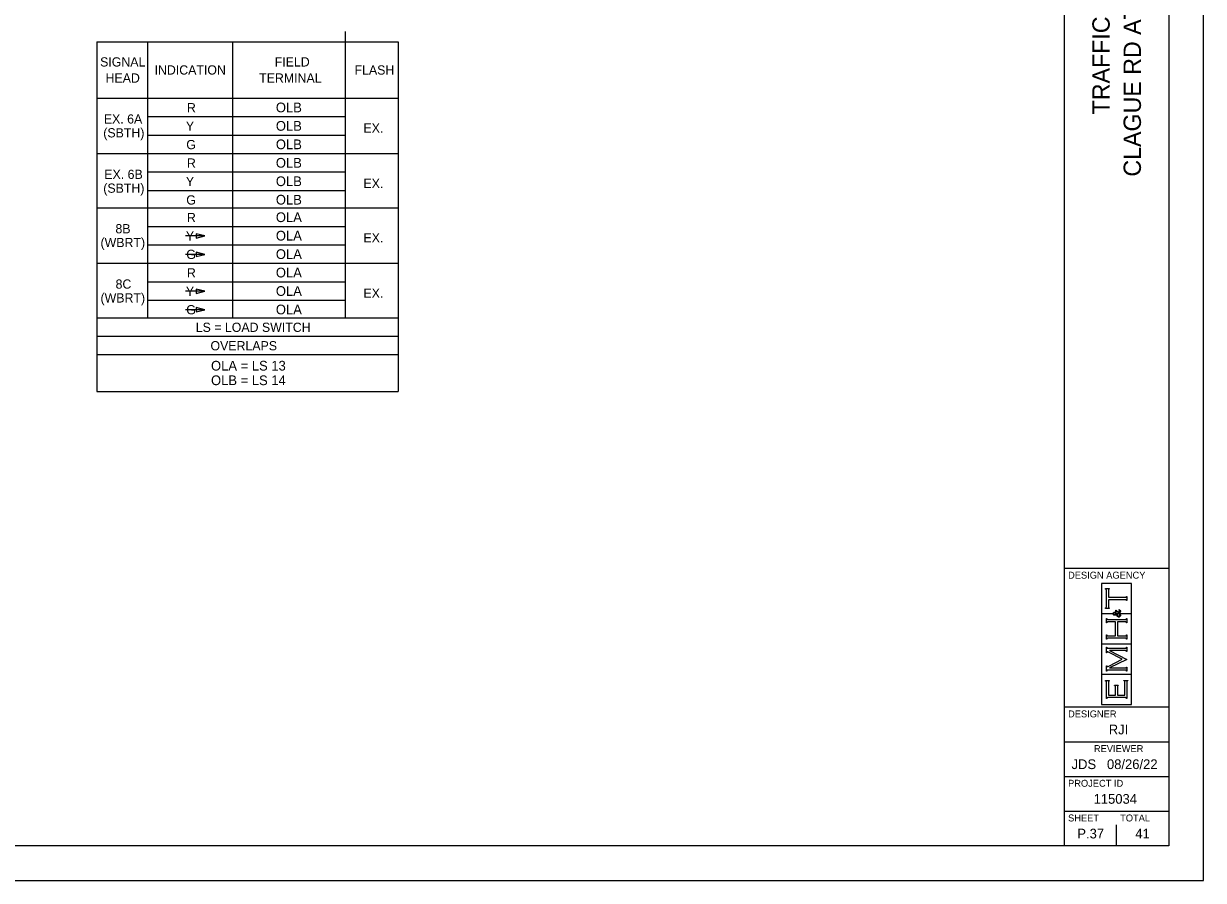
# Model space of a CAD drawing. Extents: x 680 to 2132, y 0 to 656.
# Drawn here: x 1020 to 1360, y 0 to 247 of the extents above; entities that cross this region are included whole.
import ezdxf

# ---------------------------------------------------------------- set-up
doc = ezdxf.new("R2010")
doc.units = 0
for name, color, linetype in [('SH_Border', 7, 'Continuous'), ('SH_Cut_Line', 7, 'Continuous'), ('SH_Data', 7, 'Continuous'), ('SH_Text', 7, 'Continuous'), ('ST_Text', 7, 'Continuous')]:
    doc.layers.add(name, color=color, linetype=linetype)

msp = doc.modelspace()

# ---------------------------------------------------------------- linework, layer by layer
at = {"layer": 'SH_Border'}
for p, q in [((1320, 10), (1320, 430)), ((1320, 90), (1350, 90)), ((1320, 50), (1350, 50)), ((1320, 40), (1350, 40)), ((1320, 30), (1350, 30)), ((1320, 20), (1350, 20))]:
    msp.add_line(p, q, dxfattribs=at)
msp.add_lwpolyline([(710, 430), (1350, 430), (1350, 10), (710, 10)], close=True, dxfattribs=at)
at = {"layer": 'SH_Cut_Line'}
msp.add_lwpolyline([(680, 0), (1360, 0), (1360, 440), (680, 440)], close=True, dxfattribs=at)
at = {"layer": 'SH_Data'}
for p, q in [((1072.23, 185.81), (1066.67, 185.81)), ((1072.23, 180.49), (1066.67, 180.49)), ((1072.23, 169.85), (1066.67, 169.85)), ((1072.23, 164.53), (1066.67, 164.53)), ((1339.32, 85.59), (1330.68, 85.59)), ((1330.68, 85.59), (1330.68, 76.96)), ((1339.32, 76.96), (1339.32, 85.59)), ((1331.77, 83.99), (1331.77, 84.13)), ((1331.77, 84.13), (1332.89, 84.13)), ((1331.88, 83.96), (1331.77, 83.99)), ((1331.95, 83.92), (1331.88, 83.96)), ((1331.99, 83.87), (1331.95, 83.92)), ((1332.02, 83.82), (1331.99, 83.87)), ((1332.04, 83.74), (1332.02, 83.82)), ((1332.04, 83.62), (1332.04, 83.74)), ((1332.04, 78.94), (1332.04, 83.62)), ((1332.63, 83.82), (1332.61, 83.74)), ((1332.61, 83.74), (1332.61, 83.62)), ((1332.61, 83.62), (1332.61, 81.62)), ((1332.61, 81.62), (1337.45, 81.62)), ((1332.67, 83.87), (1332.63, 83.82)), ((1332.7, 83.92), (1332.67, 83.87)), ((1332.78, 83.96), (1332.7, 83.92)), ((1332.89, 83.99), (1332.78, 83.96)), ((1332.89, 84.13), (1332.89, 83.99)), ((1337.45, 81.62), (1337.56, 81.62)), ((1337.56, 81.62), (1337.65, 81.63)), ((1337.65, 81.63), (1337.7, 81.67)), ((1337.7, 81.67), (1337.75, 81.71)), ((1337.75, 81.71), (1337.79, 81.78)), ((1337.79, 81.78), (1337.82, 81.89)), ((1337.82, 81.89), (1337.96, 81.89)), ((1337.96, 81.89), (1337.96, 80.66)), ((1331.77, 78.57), (1331.88, 78.59)), ((1331.77, 78.43), (1331.77, 78.57)), ((1332.89, 78.43), (1331.77, 78.43)), ((1331.88, 78.59), (1331.95, 78.63)), ((1331.95, 78.63), (1331.99, 78.68)), ((1331.99, 78.68), (1332.02, 78.73)), ((1332.02, 78.73), (1332.04, 78.82)), ((1332.04, 78.82), (1332.04, 78.94)), ((1337.45, 80.94), (1332.61, 80.94)), ((1332.61, 80.94), (1332.61, 78.94)), ((1332.61, 78.94), (1332.61, 78.82)), ((1332.61, 78.82), (1332.63, 78.73)), ((1332.63, 78.73), (1332.67, 78.68)), ((1332.67, 78.68), (1332.7, 78.63)), ((1332.7, 78.63), (1332.78, 78.59)), ((1332.78, 78.59), (1332.89, 78.57)), ((1332.89, 78.57), (1332.89, 78.43)), ((1337.57, 80.94), (1337.45, 80.94)), ((1337.65, 80.92), (1337.57, 80.94)), ((1337.7, 80.88), (1337.65, 80.92)), ((1337.75, 80.84), (1337.7, 80.88)), ((1337.79, 80.77), (1337.75, 80.84)), ((1337.82, 80.66), (1337.79, 80.77)), ((1337.96, 80.66), (1337.82, 80.66)), ((1330.68, 76.96), (1333.86, 76.96)), ((1333.85, 76.84), (1330.68, 76.84)), ((1330.68, 76.84), (1330.68, 68.21)), ((1332.04, 74.28), (1332.04, 75.51)), ((1332.04, 75.51), (1332.18, 75.51)), ((1332.18, 75.51), (1332.21, 75.4)), ((1332.21, 75.4), (1332.25, 75.33)), ((1332.25, 75.33), (1332.3, 75.29)), ((1332.3, 75.29), (1332.35, 75.25)), ((1332.35, 75.25), (1332.43, 75.24)), ((1332.43, 75.24), (1332.55, 75.24)), ((1332.55, 75.24), (1337.45, 75.24)), ((1333.86, 76.96), (1333.85, 76.84)), ((1334.02, 77.04), (1334.06, 77.14)), ((1334.02, 76.93), (1334.02, 77.04)), ((1334.02, 76.81), (1334.02, 76.93)), ((1334.05, 76.7), (1334.02, 76.81)), ((1334.12, 76.61), (1334.05, 76.7)), ((1334.06, 77.14), (1334.12, 77.21)), ((1334.12, 77.21), (1334.19, 77.28)), ((1334.21, 76.49), (1334.12, 76.61)), ((1334.15, 77.04), (1334.13, 76.99)), ((1334.13, 76.99), (1334.13, 76.93)), ((1334.13, 76.93), (1334.13, 76.84)), ((1334.13, 76.84), (1334.15, 76.78)), ((1334.19, 77.09), (1334.15, 77.04)), ((1334.15, 76.78), (1334.21, 76.74)), ((1334.19, 77.28), (1334.27, 77.32)), ((1334.24, 77.13), (1334.19, 77.09)), ((1334.21, 76.74), (1334.27, 76.69)), ((1334.33, 76.43), (1334.21, 76.49)), ((1334.3, 77.15), (1334.24, 77.13)), ((1334.27, 77.32), (1334.37, 77.32)), ((1334.27, 76.69), (1334.33, 76.67)), ((1334.37, 77.15), (1334.3, 77.15)), ((1334.33, 76.67), (1334.38, 76.67)), ((1334.5, 76.43), (1334.33, 76.43)), ((1334.37, 77.32), (1334.47, 77.32)), ((1334.45, 77.15), (1334.37, 77.15)), ((1334.38, 76.67), (1334.43, 76.67)), ((1334.43, 76.67), (1334.49, 76.68)), ((1334.54, 77.12), (1334.45, 77.15)), ((1334.47, 77.32), (1334.56, 77.28)), ((1334.49, 76.68), (1334.54, 76.7)), ((1334.56, 76.43), (1334.5, 76.43)), ((1334.61, 77.06), (1334.54, 77.12)), ((1334.54, 76.7), (1334.6, 76.71)), ((1334.56, 77.28), (1334.64, 77.21)), ((1334.62, 76.43), (1334.56, 76.43)), ((1334.6, 76.71), (1334.69, 76.74)), ((1334.68, 77), (1334.61, 77.06)), ((1334.68, 76.45), (1334.62, 76.43)), ((1334.64, 77.21), (1334.72, 77.14)), ((1334.75, 76.91), (1334.68, 77)), ((1334.75, 76.47), (1334.68, 76.45)), ((1334.69, 76.74), (1334.8, 76.79)), ((1334.72, 77.14), (1334.8, 77.02)), ((1334.8, 76.79), (1334.75, 76.91)), ((1334.83, 76.5), (1334.75, 76.47)), ((1334.76, 77.35), (1334.76, 77.96)), ((1334.76, 77.96), (1334.82, 77.96)), ((1334.82, 77.35), (1334.76, 77.35)), ((1334.8, 77.02), (1334.89, 76.84)), ((1334.82, 77.96), (1334.82, 77.87)), ((1334.82, 77.87), (1334.84, 77.81)), ((1334.84, 77.42), (1334.82, 77.39)), ((1334.82, 77.39), (1334.82, 77.35)), ((1334.93, 76.54), (1334.83, 76.5)), ((1334.84, 77.81), (1334.87, 77.77)), ((1334.86, 77.44), (1334.84, 77.42)), ((1334.9, 77.47), (1334.86, 77.44)), ((1334.87, 77.77), (1334.9, 77.73)), ((1334.89, 76.84), (1335.11, 76.96)), ((1334.9, 77.73), (1334.99, 77.67)), ((1334.94, 77.48), (1334.9, 77.47)), ((1335.05, 76.31), (1334.93, 76.54)), ((1334.98, 77.48), (1334.94, 77.48)), ((1335.12, 77.48), (1334.98, 77.48)), ((1334.99, 77.67), (1335.15, 77.58)), ((1335.14, 76.65), (1335.03, 76.59)), ((1335.03, 76.59), (1335.09, 76.47)), ((1335.17, 76.15), (1335.05, 76.31)), ((1335.09, 76.47), (1335.17, 76.39)), ((1335.11, 76.96), (1335.31, 77.09)), ((1335.29, 77.4), (1335.12, 77.48)), ((1335.24, 76.7), (1335.14, 76.65)), ((1335.15, 77.58), (1335.3, 77.5)), ((1335.17, 76.39), (1335.25, 76.33)), ((1335.29, 76.07), (1335.17, 76.15)), ((1335.32, 76.75), (1335.24, 76.7)), ((1335.25, 76.33), (1335.33, 76.27)), ((1335.49, 77.23), (1335.29, 77.4)), ((1335.41, 75.99), (1335.29, 76.07)), ((1335.3, 77.5), (1335.44, 77.4)), ((1335.31, 77.09), (1335.49, 77.23)), ((1335.4, 76.8), (1335.32, 76.75)), ((1335.33, 76.27), (1335.41, 76.24)), ((1335.53, 76.89), (1335.4, 76.8)), ((1335.41, 76.24), (1335.51, 76.24)), ((1335.52, 75.94), (1335.41, 75.99)), ((1335.44, 77.4), (1335.57, 77.29)), ((1335.51, 76.24), (1335.61, 76.24)), ((1335.64, 75.94), (1335.52, 75.94)), ((1335.7, 77.02), (1335.53, 76.89)), ((1335.57, 77.29), (1335.67, 77.38)), ((1335.61, 76.24), (1335.7, 76.28)), ((1335.63, 77.99), (1335.67, 78.05)), ((1335.7, 77.97), (1335.63, 77.99)), ((1335.76, 75.94), (1335.64, 75.94)), ((1335.67, 78.05), (1335.8, 78.01)), ((1335.67, 77.38), (1335.74, 77.46)), ((1335.75, 77.94), (1335.7, 77.97)), ((1335.78, 76.92), (1335.7, 77.02)), ((1335.7, 76.28), (1335.78, 76.34)), ((1335.74, 77.46), (1335.78, 77.52)), ((1335.79, 77.89), (1335.75, 77.94)), ((1335.86, 75.99), (1335.76, 75.94)), ((1335.78, 77.52), (1335.82, 77.59)), ((1335.89, 77.19), (1335.78, 77.09)), ((1335.78, 77.09), (1335.89, 76.97)), ((1335.83, 76.84), (1335.78, 76.92)), ((1335.78, 76.34), (1335.86, 76.41)), ((1335.82, 77.85), (1335.79, 77.89)), ((1335.8, 78.01), (1335.9, 77.95)), ((1335.84, 77.79), (1335.82, 77.85)), ((1335.82, 77.59), (1335.84, 77.66)), ((1335.86, 76.79), (1335.83, 76.84)), ((1335.84, 77.73), (1335.84, 77.79)), ((1335.84, 77.66), (1335.84, 77.73)), ((1335.88, 76.73), (1335.86, 76.79)), ((1335.86, 76.41), (1335.9, 76.5)), ((1335.94, 76.08), (1335.86, 75.99)), ((1335.9, 76.67), (1335.88, 76.73)), ((1335.96, 77.28), (1335.89, 77.19)), ((1335.89, 76.97), (1335.97, 76.87)), ((1335.9, 77.95), (1335.97, 77.87)), ((1335.9, 76.61), (1335.9, 76.67)), ((1335.9, 76.5), (1335.9, 76.61)), ((1336.03, 76.18), (1335.94, 76.08)), ((1336, 77.36), (1335.96, 77.28)), ((1335.97, 77.87), (1336.04, 77.8)), ((1335.97, 76.87), (1336.01, 76.77)), ((1336.05, 77.44), (1336, 77.36)), ((1336.01, 76.77), (1336.05, 76.67)), ((1336.07, 76.3), (1336.03, 76.18)), ((1336.04, 77.8), (1336.07, 77.7)), ((1336.07, 77.52), (1336.05, 77.44)), ((1336.05, 76.67), (1336.07, 76.57)), ((1336.14, 76.84), (1336.06, 76.96)), ((1336.06, 76.96), (1339.32, 76.96)), ((1336.07, 77.7), (1336.07, 77.6)), ((1336.07, 77.6), (1336.07, 77.52)), ((1336.07, 76.57), (1336.07, 76.46)), ((1336.07, 76.46), (1336.07, 76.3)), ((1339.32, 76.84), (1336.14, 76.84)), ((1337.45, 75.24), (1337.56, 75.24)), ((1337.56, 75.24), (1337.65, 75.25)), ((1337.65, 75.25), (1337.7, 75.29)), ((1337.7, 75.29), (1337.75, 75.33)), ((1337.75, 75.33), (1337.79, 75.4)), ((1337.79, 75.4), (1337.82, 75.51)), ((1337.82, 75.51), (1337.96, 75.51)), ((1337.96, 75.51), (1337.96, 74.28)), ((1339.32, 68.21), (1339.32, 76.84)), ((1332.18, 74.28), (1332.04, 74.28)), ((1332.21, 74.39), (1332.18, 74.28)), ((1332.25, 74.46), (1332.21, 74.39)), ((1332.3, 74.5), (1332.25, 74.46)), ((1332.35, 74.54), (1332.3, 74.5)), ((1332.43, 74.56), (1332.35, 74.54)), ((1332.55, 74.56), (1332.43, 74.56)), ((1334.63, 74.56), (1332.55, 74.56)), ((1334.63, 70.49), (1334.63, 74.56)), ((1337.45, 74.56), (1335.2, 74.56)), ((1335.2, 74.56), (1335.2, 70.49)), ((1337.57, 74.56), (1337.45, 74.56)), ((1337.65, 74.54), (1337.57, 74.56)), ((1337.7, 74.5), (1337.65, 74.54)), ((1337.75, 74.46), (1337.7, 74.5)), ((1337.79, 74.39), (1337.75, 74.46)), ((1337.82, 74.28), (1337.79, 74.39)), ((1337.96, 74.28), (1337.82, 74.28)), ((1330.68, 68.21), (1339.32, 68.21)), ((1339.32, 68.09), (1330.68, 68.09)), ((1330.68, 68.09), (1330.68, 59.45)), ((1332.04, 69.54), (1332.04, 70.77)), ((1332.04, 70.77), (1332.18, 70.77)), ((1332.18, 69.54), (1332.04, 69.54)), ((1332.18, 70.77), (1332.21, 70.66)), ((1332.21, 69.65), (1332.18, 69.54)), ((1332.21, 70.66), (1332.25, 70.59)), ((1332.25, 69.72), (1332.21, 69.65)), ((1332.25, 70.59), (1332.3, 70.55)), ((1332.3, 69.76), (1332.25, 69.72)), ((1332.3, 70.55), (1332.35, 70.51)), ((1332.35, 69.8), (1332.3, 69.76)), ((1332.35, 70.51), (1332.43, 70.49)), ((1332.43, 69.81), (1332.35, 69.8)), ((1332.43, 70.49), (1332.55, 70.49)), ((1332.55, 69.81), (1332.43, 69.81)), ((1332.55, 70.49), (1334.63, 70.49)), ((1337.45, 69.81), (1332.55, 69.81)), ((1335, 70), (1335, 70)), ((1335.2, 70.49), (1337.45, 70.49)), ((1337.45, 70.49), (1337.57, 70.49)), ((1337.57, 69.81), (1337.45, 69.81)), ((1337.57, 70.49), (1337.65, 70.51)), ((1337.65, 69.8), (1337.57, 69.81)), ((1337.65, 70.51), (1337.7, 70.55)), ((1337.7, 69.76), (1337.65, 69.8)), ((1337.7, 70.55), (1337.75, 70.58)), ((1337.75, 69.72), (1337.7, 69.76)), ((1337.75, 70.58), (1337.79, 70.66)), ((1337.79, 69.65), (1337.75, 69.72)), ((1337.79, 70.66), (1337.82, 70.77)), ((1337.82, 69.54), (1337.79, 69.65)), ((1337.82, 70.77), (1337.96, 70.77)), ((1337.96, 69.54), (1337.82, 69.54)), ((1337.96, 70.77), (1337.96, 69.54)), ((1339.32, 59.45), (1339.32, 68.09)), ((1332.04, 65.65), (1332.04, 67.2)), ((1332.04, 67.2), (1332.18, 67.2)), ((1332.18, 65.65), (1332.04, 65.65)), ((1332.18, 67.2), (1332.21, 67.09)), ((1332.23, 65.8), (1332.18, 65.65)), ((1332.21, 67.09), (1332.25, 67.02)), ((1332.29, 65.87), (1332.23, 65.8)), ((1332.25, 67.02), (1332.3, 66.98)), ((1332.37, 65.87), (1332.29, 65.87)), ((1332.3, 66.98), (1332.35, 66.94)), ((1332.35, 66.94), (1332.43, 66.92)), ((1332.43, 65.87), (1332.37, 65.87)), ((1332.43, 66.92), (1332.55, 66.92)), ((1332.52, 65.83), (1332.43, 65.87)), ((1332.66, 65.76), (1332.52, 65.83)), ((1332.55, 66.92), (1337.45, 66.92)), ((1336.62, 63.78), (1332.66, 65.76)), ((1337.44, 66.24), (1332.97, 66.24)), ((1332.97, 66.24), (1337.96, 63.73)), ((1337.57, 66.24), (1337.44, 66.24)), ((1337.45, 66.92), (1337.56, 66.92)), ((1337.56, 66.92), (1337.65, 66.94)), ((1337.65, 66.23), (1337.57, 66.24)), ((1337.65, 66.94), (1337.7, 66.98)), ((1337.7, 66.19), (1337.65, 66.23)), ((1337.7, 66.98), (1337.75, 67.02)), ((1337.75, 66.15), (1337.7, 66.19)), ((1337.75, 67.02), (1337.79, 67.09)), ((1337.79, 66.08), (1337.75, 66.15)), ((1337.79, 67.09), (1337.82, 67.2)), ((1337.82, 65.97), (1337.79, 66.08)), ((1337.82, 67.2), (1337.96, 67.2)), ((1337.96, 65.97), (1337.82, 65.97)), ((1337.96, 67.2), (1337.96, 65.97)), ((1332.04, 60.35), (1332.04, 61.88)), ((1332.04, 61.88), (1332.18, 61.88)), ((1332.18, 61.88), (1332.23, 61.74)), ((1332.23, 61.74), (1332.29, 61.67)), ((1332.29, 61.67), (1332.36, 61.67)), ((1332.36, 61.67), (1332.4, 61.67)), ((1332.4, 61.67), (1332.51, 61.71)), ((1332.51, 61.71), (1332.7, 61.81)), ((1332.7, 61.81), (1336.62, 63.78)), ((1337.96, 63.73), (1332.97, 61.24)), ((1332.97, 61.24), (1337.44, 61.24)), ((1337.44, 61.24), (1337.56, 61.24)), ((1337.56, 61.24), (1337.65, 61.26)), ((1337.65, 61.26), (1337.7, 61.3)), ((1337.7, 61.3), (1337.75, 61.33)), ((1337.75, 61.33), (1337.79, 61.41)), ((1337.79, 61.41), (1337.82, 61.52)), ((1337.82, 61.52), (1337.96, 61.52)), ((1337.96, 61.52), (1337.96, 60.35)), ((1330.68, 59.45), (1339.32, 59.45)), ((1339.32, 59.34), (1330.68, 59.34)), ((1330.68, 59.34), (1330.68, 50.7)), ((1332.18, 60.35), (1332.04, 60.35)), ((1332.21, 60.46), (1332.18, 60.35)), ((1332.25, 60.53), (1332.21, 60.46)), ((1332.3, 60.57), (1332.25, 60.53)), ((1332.35, 60.6), (1332.3, 60.57)), ((1332.43, 60.62), (1332.35, 60.6)), ((1332.55, 60.62), (1332.43, 60.62)), ((1337.45, 60.62), (1332.55, 60.62)), ((1337.57, 60.62), (1337.45, 60.62)), ((1337.65, 60.6), (1337.57, 60.62)), ((1337.7, 60.57), (1337.65, 60.6)), ((1337.75, 60.53), (1337.7, 60.57)), ((1337.79, 60.46), (1337.75, 60.53)), ((1337.82, 60.35), (1337.79, 60.46)), ((1337.96, 60.35), (1337.82, 60.35)), ((1339.32, 50.7), (1339.32, 59.34)), ((1331.77, 57.48), (1331.77, 57.62)), ((1331.77, 57.62), (1332.89, 57.62)), ((1331.88, 57.46), (1331.77, 57.48)), ((1331.95, 57.42), (1331.88, 57.46)), ((1331.99, 57.37), (1331.95, 57.42)), ((1332.02, 57.32), (1331.99, 57.37)), ((1332.04, 57.23), (1332.02, 57.32)), ((1332.04, 57.11), (1332.04, 57.23)), ((1332.04, 52.42), (1332.04, 57.11)), ((1332.63, 57.32), (1332.61, 57.23)), ((1332.61, 57.23), (1332.61, 57.11)), ((1332.61, 57.11), (1332.61, 53.37)), ((1332.67, 57.37), (1332.63, 57.32)), ((1332.71, 57.42), (1332.67, 57.37)), ((1332.78, 57.46), (1332.71, 57.42)), ((1332.89, 57.48), (1332.78, 57.46)), ((1332.89, 57.62), (1332.89, 57.48)), ((1334.35, 56.19), (1334.35, 56.33)), ((1334.35, 56.33), (1335.48, 56.33)), ((1334.46, 56.16), (1334.35, 56.19)), ((1334.54, 56.13), (1334.46, 56.16)), ((1334.57, 56.08), (1334.54, 56.13)), ((1334.61, 56.03), (1334.57, 56.08)), ((1334.63, 55.94), (1334.61, 56.03)), ((1334.63, 55.82), (1334.63, 55.94)), ((1334.63, 53.37), (1334.63, 55.82)), ((1335.22, 56.03), (1335.2, 55.94)), ((1335.2, 55.94), (1335.2, 55.82)), ((1335.2, 55.82), (1335.2, 53.37)), ((1335.26, 56.08), (1335.22, 56.03)), ((1335.29, 56.13), (1335.26, 56.08)), ((1335.37, 56.16), (1335.29, 56.13)), ((1335.48, 56.19), (1335.37, 56.16)), ((1335.48, 56.33), (1335.48, 56.19)), ((1337.11, 57.55), (1337.11, 57.68)), ((1337.11, 57.68), (1338.23, 57.68)), ((1337.22, 57.52), (1337.11, 57.55)), ((1337.29, 57.48), (1337.22, 57.52)), ((1337.33, 57.43), (1337.29, 57.48)), ((1337.37, 57.38), (1337.33, 57.43)), ((1337.39, 57.29), (1337.37, 57.38)), ((1337.39, 57.17), (1337.39, 57.29)), ((1337.39, 53.37), (1337.39, 57.17)), ((1337.98, 57.38), (1337.96, 57.29)), ((1337.96, 57.29), (1337.96, 57.17)), ((1337.96, 57.17), (1337.96, 52.42)), ((1338.01, 57.43), (1337.98, 57.38)), ((1338.05, 57.48), (1338.01, 57.43)), ((1338.12, 57.52), (1338.05, 57.48)), ((1338.23, 57.55), (1338.12, 57.52)), ((1338.23, 57.68), (1338.23, 57.55)), ((1332.18, 52.42), (1332.04, 52.42)), ((1332.21, 52.53), (1332.18, 52.42)), ((1332.25, 52.6), (1332.21, 52.53)), ((1332.3, 52.64), (1332.25, 52.6)), ((1332.35, 52.68), (1332.3, 52.64)), ((1332.43, 52.69), (1332.35, 52.68)), ((1332.55, 52.69), (1332.43, 52.69)), ((1337.45, 52.69), (1332.55, 52.69)), ((1332.61, 53.37), (1334.63, 53.37)), ((1335.2, 53.37), (1337.39, 53.37)), ((1337.57, 52.69), (1337.45, 52.69)), ((1337.65, 52.68), (1337.57, 52.69)), ((1337.7, 52.64), (1337.65, 52.68)), ((1337.75, 52.6), (1337.7, 52.64)), ((1337.79, 52.53), (1337.75, 52.6)), ((1337.82, 52.42), (1337.79, 52.53)), ((1337.96, 52.42), (1337.82, 52.42)), ((1330.68, 50.7), (1339.32, 50.7)), ((1335, 10), (1335, 16)), ((1327.5, 13.5), (1327.5, 13.5))]:
    msp.add_line(p, q, dxfattribs=at)
for points in [[(1069.73, 185.19), (1072.23, 185.81), (1069.73, 186.44)], [(1069.73, 179.87), (1072.23, 180.49), (1069.73, 181.12)], [(1069.73, 169.23), (1072.23, 169.85), (1069.73, 170.48)], [(1069.73, 163.91), (1072.23, 164.53), (1069.73, 165.16)]]:
    msp.add_lwpolyline(points, close=True, dxfattribs=at)
at = {"layer": 'SH_Text'}
msp.add_line((1320, 90), (1350, 90), dxfattribs=at)
at = {"layer": 'ST_Text'}
for p, q in [((1041.13, 241.79), (1127.95, 241.79)), ((1041.13, 241.79), (1041.13, 140.94)), ((1055.69, 241.79), (1055.69, 162.22)), ((1080.21, 241.79), (1080.21, 162.22)), ((1112.66, 244.71), (1112.66, 162.22)), ((1127.95, 241.79), (1127.95, 140.94)), ((1041.13, 225.52), (1127.95, 225.52)), ((1055.69, 220.2), (1112.66, 220.2)), ((1055.69, 214.88), (1112.66, 214.88)), ((1041.13, 209.56), (1127.95, 209.56)), ((1055.69, 204.24), (1112.66, 204.24)), ((1055.69, 198.92), (1112.66, 198.92)), ((1041.13, 193.87), (1127.95, 193.87)), ((1055.69, 188.55), (1112.66, 188.55)), ((1055.69, 183.23), (1112.66, 183.23)), ((1041.13, 177.91), (1127.95, 177.91)), ((1055.69, 172.59), (1112.66, 172.59)), ((1055.69, 167.27), (1112.66, 167.27)), ((1041.13, 162.22), (1127.95, 162.22)), ((1041.13, 156.9), (1127.95, 156.9)), ((1041.13, 151.58), (1127.95, 151.58)), ((1041.13, 140.94), (1127.95, 140.94))]:
    msp.add_line(p, q, dxfattribs=at)

# ---------------------------------------------------------------- texts
at = {"layer": 'SH_Data'}
for s, p in [('CLAGUE RD AT I-480 WB EXIT RAMP', (1342, 202.91)), ('TRAFFIC SIGNAL DETAILS', (1333, 220.85))]:
    msp.add_text(s, height=5, rotation=90, dxfattribs=at).set_placement(p)
for s, height, p in [('DESIGN AGENCY', 2, (1321, 87)), ('DESIGNER', 2, (1321, 47)), ('RJI', 2.8, (1332.73, 42.1)), ('REVIEWER', 2, (1328.44, 37)), ('JDS', 2.8, (1322.01, 32.1)), ('08/26/22', 2.8, (1332.21, 32.1)), ('PROJECT ID', 2, (1321, 27)), ('115034', 2.8, (1328.36, 22.1)), ('SHEET', 2, (1321, 17)), ('TOTAL', 2, (1336, 17)), ('P.37', 2.8, (1323.67, 12.1)), ('41', 2.8, (1340.38, 12.1))]:
    msp.add_text(s, height=height, dxfattribs=at).set_placement(p)
at = {"layer": 'SH_Text'}
for s, p in [('OLB', (1092.7, 221.45)), ('OLB', (1092.7, 216.13)), ('OLB', (1092.7, 210.81)), ('OLB', (1092.7, 205.49)), ('OLB', (1092.7, 200.17)), ('OLB', (1092.7, 194.85)), ('OLA', (1092.7, 189.8)), ('OLA', (1092.7, 184.48)), ('OLA', (1092.7, 179.16)), ('OLA', (1092.7, 173.84)), ('OLA', (1092.7, 168.52)), ('OLA', (1092.7, 163.2)), ('OLA = LS 13', (1074.01, 146.99)), ('OLB = LS 14', (1074.01, 142.79))]:
    msp.add_text(s, height=2.8, dxfattribs=at).set_placement(p)
at = {"layer": 'ST_Text'}
for s, p in [('SIGNAL', (1042.05, 234.65)), ('INDICATION', (1057.74, 232.33)), ('FIELD', (1092.37, 234.65)), ('FLASH', (1115.37, 232.33)), ('HEAD', (1043.62, 230)), ('TERMINAL', (1087.89, 230)), ('R', (1067.07, 221.45)), ('EX. 6A', (1043.12, 218.2)), ('Y', (1066.77, 216.13)), ('EX.', (1117.94, 215.58)), ('(SBTH)', (1042.96, 214.21)), ('G', (1066.88, 210.81)), ('R', (1067.07, 205.49)), ('EX. 6B', (1043.26, 202.24)), ('(SBTH)', (1042.96, 198.25)), ('Y', (1066.77, 200.17)), ('EX.', (1117.94, 199.62)), ('G', (1066.88, 194.85)), ('R', (1067.07, 189.8)), ('8B', (1046.47, 186.56)), ('Y', (1066.77, 184.48)), ('(WBRT)', (1042.17, 182.57)), ('EX.', (1117.94, 183.94)), ('G', (1066.88, 179.16)), ('R', (1067.07, 173.84)), ('8C', (1046.51, 170.6)), ('Y', (1066.77, 168.52)), ('EX.', (1117.94, 167.98)), ('(WBRT)', (1042.17, 166.61)), ('G', (1066.88, 163.2)), ('LS = LOAD SWITCH', (1069.61, 158.14)), ('OVERLAPS', (1073.86, 152.82))]:
    msp.add_text(s, height=2.66, dxfattribs=at).set_placement(p)

doc.saveas('drawing.dxf')
